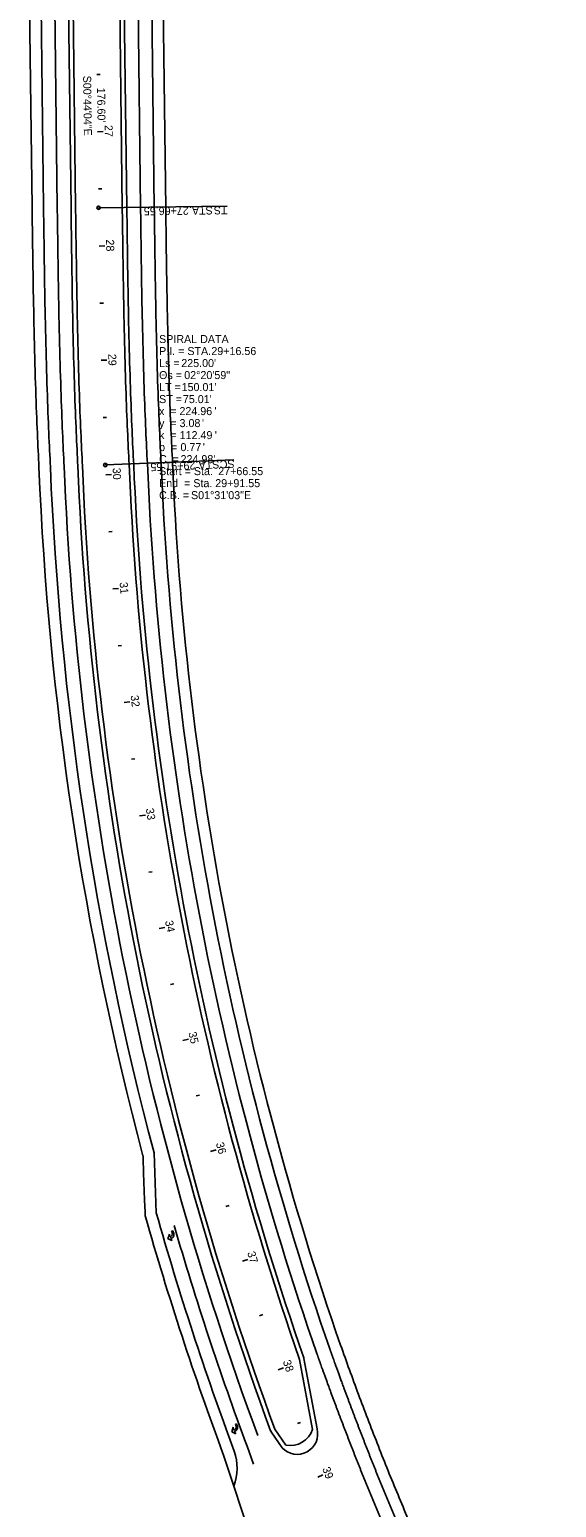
# Model space of a CAD drawing. Extents: x 76539 to 88870, y 518807 to 527554.
# Drawn here: x 87665 to 88126, y 519909 to 521202 of the extents above; entities that cross this region are included whole.
import ezdxf

# ---------------------------------------------------------------- set-up
doc = ezdxf.new("R2010")
doc.units = 0
for name, color, linetype in [('Default', 7, 'Continuous'), ('GE_P_Alignment_100_Bearings', 7, 'Continuous'), ('GE_P_Alignment_100_Cardinal_Points', 7, 'Continuous'), ('GE_P_Alignment_100_Curve_Data', 7, 'Continuous'), ('GE_P_Alignment_100_Distances', 7, 'Continuous'), ('GE_P_Alignment_100_Stations', 7, 'Continuous'), ('PM_P_Cells', 7, 'Continuous'), ('PM_P_Channelizing_Line', 7, 'Continuous'), ('PM_P_Edge_Line', 7, 'Continuous'), ('PM_P_Lane_Line', 7, 'Continuous'), ('PV_P_Joint', 7, 'Continuous'), ('PV_P_Shoulder', 7, 'Continuous'), ('XS_P_Pavt_Surface', 7, 'Continuous')]:
    doc.layers.add(name, color=color, linetype=linetype)

msp = doc.modelspace()

# ---------------------------------------------------------------- linework, layer by layer
at = {"layer": 'Default'}
for points, degree in [([(87764.1, 520216.7), (87764.1, 520215.8), (87764.1, 520214.1), (87764.2, 520211.5), (87764.3, 520208.8), (87764.4, 520206.2), (87764.5, 520203.6), (87764.5, 520201), (87764.6, 520198.4), (87764.7, 520195.7), (87764.8, 520193.1), (87764.9, 520190.5), (87765, 520187.9), (87765.1, 520185.2), (87765.2, 520182.6), (87765.3, 520180), (87765.4, 520177.3), (87765.6, 520174.7), (87765.7, 520172.1), (87765.8, 520169.5), (87765.9, 520166.8), (87766, 520165.1), (87766, 520164.2)], 3), ([(87927.4, 520047.8), (87928.8, 520043.7), (87933.9, 520029.5), (87943.4, 520003.7), (87951.1, 519983.3), (87959.5, 519961.6), (87967.9, 519940.3), (87976.6, 519919), (87985.5, 519897.8), (87994.5, 519876.7), (88003.7, 519855.7), (88013.1, 519834.7), (88022.7, 519813.8), (88032.4, 519793), (88042.4, 519772.3), (88052.5, 519751.6), (88062.8, 519731.1), (88073.2, 519710.7), (88084, 519690), (88094.2, 519670.8), (88107.3, 519646.6), (88114.7, 519633.5), (88116.8, 519629.7)], 2), ([(87936.8, 520051.1), (87939.4, 520044), (87944.5, 520029.6), (87952.4, 520008.1), (87960.5, 519986.7), (87968.8, 519965.3), (87977.2, 519944), (87985.9, 519922.8), (87994.7, 519901.7), (88003.7, 519880.6), (88012.9, 519859.7), (88022.3, 519838.8), (88031.8, 519817.9), (88041.5, 519797.2), (88051.4, 519776.6), (88061.5, 519756), (88071.7, 519735.5), (88082.1, 519715.1), (88092.7, 519694.9), (88103.5, 519674.7), (88114.4, 519654.5), (88121.8, 519641.2), (88125.5, 519634.5)], 3), ([(87916.1, 520043.7), (87917.5, 520039.7), (87922.6, 520025.4), (87932.1, 519999.5), (87939.9, 519979), (87948.3, 519957.2), (87956.8, 519935.9), (87965.5, 519914.5), (87974.4, 519893.2), (87983.5, 519871.9), (87992.8, 519850.8), (88002.2, 519829.7), (88011.8, 519808.8), (88021.6, 519787.9), (88031.6, 519767), (88041.7, 519746.3), (88052.1, 519725.7), (88062.5, 519705.2), (88073.3, 519684.4), (88083.6, 519665.1), (88096.8, 519640.9), (88104.2, 519627.6), (88106.3, 519623.9)], 2)]:
    msp.add_open_spline(points, degree=degree, dxfattribs=at)
at = {"layer": 'GE_P_Alignment_100_Cardinal_Points'}
for p, q in [((87725.2, 521045.7), (87837.7, 521047.1)), ((87731.1, 520820.8), (87843.5, 520825.4))]:
    msp.add_line(p, q, dxfattribs=at)
for centre in [(87725.2, 521045.7), (87731.1, 520820.8)]:
    msp.add_circle(centre, 1.5, dxfattribs=at)
at = {"layer": 'GE_P_Alignment_100_Stations'}
for p, q in [((87723.7, 521162.2), (87726.7, 521162.3)), ((87724.3, 521112.2), (87729.3, 521112.3)), ((87725, 521062.2), (87728, 521062.3)), ((87725.6, 521012.2), (87730.6, 521012.3)), ((87726.4, 520962.2), (87729.4, 520962.3)), ((87727.5, 520912.3), (87732.5, 520912.4)), ((87729.2, 520862.3), (87732.2, 520862.4)), ((87731.5, 520812.3), (87736.5, 520812.6)), ((87734.2, 520762.4), (87737.2, 520762.6)), ((87737.7, 520712.5), (87742.7, 520712.9)), ((87742.2, 520662.7), (87745.2, 520663)), ((87747.6, 520613), (87752.6, 520613.6)), ((87753.9, 520563.4), (87756.9, 520563.8)), ((87761.1, 520514), (87766.1, 520514.7)), ((87769.2, 520464.6), (87772.2, 520465.1)), ((87778.2, 520415.4), (87783.1, 520416.4)), ((87788.1, 520366.4), (87791, 520367)), ((87798.9, 520317.6), (87803.8, 520318.7)), ((87810.6, 520269), (87813.5, 520269.7)), ((87823.1, 520220.6), (87827.9, 520221.9)), ((87836.6, 520172.4), (87839.4, 520173.3)), ((87850.9, 520124.5), (87855.6, 520126)), ((87866, 520076.9), (87868.9, 520077.8)), ((87882.1, 520029.5), (87886.8, 520031.2)), ((87899, 519982.5), (87901.8, 519983.5)), ((87916.8, 519935.7), (87921.4, 519937.6))]:
    msp.add_line(p, q, dxfattribs=at)
at = {"layer": 'PM_P_Cells'}
for p, q in [((87786.9, 520150.1), (87786.9, 520150.1)), ((87789.1, 520150.8), (87790.1, 520151.2)), ((87789.7, 520149.1), (87789.1, 520150.8)), ((87790.1, 520151.2), (87790.9, 520148.8)), ((87785.8, 520144), (87787.2, 520148.1)), ((87789.5, 520142.5), (87785.8, 520144)), ((87787.2, 520148.1), (87787.6, 520145.9)), ((87787.6, 520145.9), (87788.3, 520146.2)), ((87788.8, 520144.6), (87788.2, 520144.4)), ((87788.2, 520144.4), (87789.5, 520142.5)), ((87789.5, 520142.5), (87789.5, 520142.5)), ((87842.6, 519981.3), (87842.6, 519981.3)), ((87844.8, 519982.1), (87845.8, 519982.4)), ((87845.4, 519980.3), (87844.8, 519982.1)), ((87845.8, 519982.4), (87846.6, 519980)), ((87841.6, 519975.2), (87842.9, 519979.4)), ((87845.2, 519973.7), (87841.6, 519975.2)), ((87842.9, 519979.4), (87843.3, 519977.1)), ((87843.3, 519977.1), (87844, 519977.4)), ((87844.5, 519975.8), (87843.9, 519975.6)), ((87843.9, 519975.6), (87845.2, 519973.7)), ((87845.2, 519973.7), (87845.2, 519973.7))]:
    msp.add_line(p, q, dxfattribs=at)
for centre, radius, start in [((87787.5, 520148.3), 2.3, 289.0234), ((87787.8, 520147.7), 3.28, 288.1149), ((87843.3, 519979.5), 2.3, 289.0234), ((87843.5, 519979), 3.28, 288.1149)]:
    msp.add_arc(centre, radius, start, 19.0234, dxfattribs=at)
at = {"layer": 'PM_P_Channelizing_Line'}
msp.add_line((87860.8, 519947.1), (87855.1, 519962.7), dxfattribs=at)
msp.add_arc((90472.1, 520933.7), 2791.4, 196.1811, 200.3571, dxfattribs=at)
at = {"layer": 'PM_P_Edge_Line'}
for p, q in [((87674.9, 521221.7), (87677.1, 521046.1)), ((87698.9, 521222), (87701.1, 521045.9)), ((87747.7, 521222.6), (87749.9, 521045.5)), ((87771.7, 521222.9), (87773.9, 521045.3)), ((87773.7, 520219.3), (87775.6, 520166.9)), ((87904.8, 520039.4), (87904.7, 520040)), ((87904.8, 520039.4), (87916.3, 519978)), ((87876.1, 519975.3), (87875.7, 519976.2)), ((87876.1, 519975.3), (87885.7, 519961.4))]:
    msp.add_line(p, q, dxfattribs=at)
for centre, radius, start, end in [((90472.1, 520933.7), 2718.5, 182.3628, 199.1928), ((90472.1, 520933.7), 2694.5, 182.3667, 199.1928), ((90472.1, 520933.7), 2791.4, 182.3509, 194.829), ((90472.1, 520933.7), 2767.4, 182.3548, 200.242), ((90472.1, 520933.7), 2803.4, 195.8733, 200.3571), ((87898.9, 519973.5), 17.9, 222.4917, 14.6896), ((87801.2, 519943.8), 45.1, 339.3713, 18.9583)]:
    msp.add_arc(centre, radius, start, end, dxfattribs=at)
for points in [[(87677.1, 521046.1), (87677.2, 521036.6), (87677.5, 521017.7), (87678, 520979.9), (87678.9, 520932.6), (87680.2, 520885.3), (87681.7, 520847.5), (87682.6, 520828.6), (87683.1, 520819.2)], [(87701.1, 521045.9), (87701.2, 521036.5), (87701.5, 521017.6), (87702, 520980), (87702.9, 520932.9), (87704.2, 520885.8), (87705.7, 520848.2), (87706.6, 520829.4), (87707.1, 520820)], [(87749.9, 521045.5), (87750.1, 521036.2), (87750.3, 521017.5), (87750.8, 520980.2), (87751.7, 520933.5), (87753, 520886.9), (87754.5, 520849.6), (87755.4, 520830.9), (87755.9, 520821.6)], [(87773.9, 521045.3), (87774.1, 521036), (87774.3, 521017.4), (87774.8, 520980.3), (87775.7, 520933.8), (87777, 520887.4), (87778.5, 520850.3), (87779.4, 520831.7), (87779.9, 520822.4)]]:
    msp.add_open_spline(points, degree=3, dxfattribs=at)
at = {"layer": 'PM_P_Lane_Line'}
for p, q in [((87686.9, 521221.8), (87689.1, 521046)), ((87759.7, 521222.7), (87761.9, 521045.4))]:
    msp.add_line(p, q, dxfattribs=at)
for radius, start, end in [(2706.5, 182.3648, 199.1928), (2779.4, 182.3528, 200.242)]:
    msp.add_arc((90472.1, 520933.7), radius, start, end, dxfattribs=at)
for points in [[(87689.1, 521046), (87689.2, 521036.5), (87689.5, 521017.7), (87690, 520979.9), (87690.9, 520932.7), (87692.2, 520885.6), (87693.7, 520847.9), (87694.6, 520829), (87695.1, 520819.6)], [(87761.9, 521045.4), (87762.1, 521036.1), (87762.3, 521017.5), (87762.8, 520980.2), (87763.7, 520933.7), (87765, 520887.1), (87766.5, 520849.9), (87767.4, 520831.3), (87767.9, 520822)]]:
    msp.add_open_spline(points, degree=3, dxfattribs=at)
at = {"layer": 'PV_P_Joint'}
msp.add_line((87834.5, 519955), (87870.6, 519845.6), dxfattribs=at)
at = {"layer": 'PV_P_Shoulder'}
for p, q in [((87664.9, 521221.5), (87667.1, 521046.1)), ((87702.9, 521222), (87705.1, 521045.8)), ((87743.7, 521222.5), (87745.9, 521045.5)), ((87781.7, 521223), (87783.9, 521045.2)), ((87900.9, 520038.7), (87912.3, 519977.3)), ((87879.4, 519977.6), (87889, 519963.7))]:
    msp.add_line(p, q, dxfattribs=at)
for centre, radius, start, end in [((90472.1, 520933.7), 2722.5, 182.3621, 199.1928), ((90472.1, 520933.7), 2684.5, 182.3684, 199.1928), ((90472.1, 520933.7), 2801.4, 182.3493, 194.829), ((90472.1, 520933.7), 2763.4, 182.3554, 200.242), ((90472.1, 520933.7), 2813.4, 195.8733, 200.3571), ((87892.8, 519984), 20.6, 259.4675, 341.1834)]:
    msp.add_arc(centre, radius, start, end, dxfattribs=at)
for points in [[(87667.1, 521046.1), (87667.2, 521036.7), (87667.5, 521017.7), (87668, 520979.8), (87668.9, 520932.5), (87670.2, 520885.1), (87671.7, 520847.2), (87672.6, 520828.3), (87673.1, 520818.9)], [(87705.1, 521045.8), (87705.2, 521036.4), (87705.5, 521017.6), (87706, 520980), (87706.9, 520932.9), (87708.2, 520885.9), (87709.7, 520848.3), (87710.6, 520829.5), (87711.1, 520820.1)], [(87745.9, 521045.5), (87746.1, 521036.2), (87746.3, 521017.5), (87746.8, 520980.2), (87747.7, 520933.5), (87749, 520886.8), (87750.5, 520849.5), (87751.4, 520830.8), (87751.9, 520821.5)], [(87783.9, 521045.2), (87784.1, 521036), (87784.3, 521017.4), (87784.8, 520980.3), (87785.7, 520934), (87787, 520887.6), (87788.5, 520850.5), (87789.4, 520832), (87789.9, 520822.7)]]:
    msp.add_open_spline(points, degree=3, dxfattribs=at)
at = {"layer": 'XS_P_Pavt_Surface'}
for p, q in [((87667.1, 521046.1), (87664.9, 521221.5)), ((87702.9, 521222), (87705.1, 521045.8)), ((87745.9, 521045.5), (87743.7, 521222.5)), ((87781.7, 521223), (87783.9, 521045.2)), ((87912.3, 519977.3), (87900.9, 520038.7)), ((87879.4, 519977.6), (87889, 519963.7)), ((87870.6, 519845.6), (87834.5, 519955))]:
    msp.add_line(p, q, dxfattribs=at)
for centre, radius, start, end in [((90472.1, 520933.7), 2722.5, 182.3621, 199.1928), ((90472.1, 520933.7), 2684.5, 182.3684, 199.1928), ((90472.1, 520933.7), 2801.4, 182.3493, 194.829), ((90472.1, 520933.7), 2763.4, 182.3554, 200.242), ((90472.1, 520933.7), 2813.4, 195.8733, 200.3571), ((87892.8, 519984), 20.6, 259.4675, 341.1834)]:
    msp.add_arc(centre, radius, start, end, dxfattribs=at)
for points in [[(87673.1, 520818.9), (87672.6, 520828.3), (87671.7, 520847.2), (87670.2, 520885.1), (87668.9, 520932.5), (87668, 520979.8), (87667.5, 521017.7), (87667.2, 521036.7), (87667.1, 521046.1)], [(87705.1, 521045.8), (87705.2, 521036.4), (87705.5, 521017.6), (87706, 520980), (87706.9, 520932.9), (87708.2, 520885.9), (87709.7, 520848.3), (87710.6, 520829.5), (87711.1, 520820.1)], [(87751.9, 520821.5), (87751.4, 520830.8), (87750.5, 520849.5), (87749, 520886.8), (87747.7, 520933.5), (87746.8, 520980.2), (87746.3, 521017.5), (87746.1, 521036.2), (87745.9, 521045.5)], [(87783.9, 521045.2), (87784.1, 521036), (87784.3, 521017.4), (87784.8, 520980.3), (87785.7, 520934), (87787, 520887.6), (87788.5, 520850.5), (87789.4, 520832), (87789.9, 520822.7)], [(87766, 520164.2), (87766, 520165.1), (87765.9, 520166.8), (87765.8, 520169.5), (87765.7, 520172.1), (87765.6, 520174.7), (87765.4, 520177.3), (87765.3, 520180), (87765.2, 520182.6), (87765.1, 520185.2), (87765, 520187.9), (87764.9, 520190.5), (87764.8, 520193.1), (87764.7, 520195.7), (87764.6, 520198.4), (87764.5, 520201), (87764.5, 520203.6), (87764.4, 520206.2), (87764.3, 520208.8), (87764.2, 520211.5), (87764.1, 520214.1), (87764.1, 520215.8), (87764.1, 520216.7)], [(87936.8, 520051.1), (87939.4, 520044), (87944.5, 520029.6), (87952.4, 520008.1), (87960.5, 519986.7), (87968.8, 519965.3), (87977.2, 519944), (87985.9, 519922.8), (87994.7, 519901.7), (88003.7, 519880.6), (88012.9, 519859.7), (88022.3, 519838.8), (88031.8, 519817.9), (88041.5, 519797.2), (88051.4, 519776.6), (88061.5, 519756), (88071.7, 519735.5), (88082.1, 519715.1), (88092.7, 519694.9), (88103.5, 519674.7), (88114.4, 519654.5), (88121.8, 519641.2), (88125.5, 519634.5)]]:
    msp.add_open_spline(points, degree=3, dxfattribs=at)

# ---------------------------------------------------------------- texts
at = {"layer": 'GE_P_Alignment_100_Bearings'}
msp.add_text('S00°44\'04"E', height=7, rotation=270.7344, dxfattribs=at).set_placement((87711.7, 521161.2))
at = {"layer": 'GE_P_Alignment_100_Cardinal_Points'}
for s, rotation, p in [('27+66.55', 180.7344, (87804, 521046.6)), (' STA. ', 180.7344, (87827.6, 521046.9)), ('TS', 180.7344, (87837.9, 521047)), ('29+91.55', 182.3587, (87809.7, 520823.9)), (' STA. ', 182.3587, (87833.3, 520824.9)), ('SC', 182.3587, (87844, 520825.3))]:
    msp.add_text(s, height=7, rotation=rotation, dxfattribs=at).set_placement(p)
at = {"layer": 'GE_P_Alignment_100_Curve_Data'}
for s, p in [('SPIRAL DATA', (87778.1, 520927.4)), ('P.I. = STA. ', (87778.1, 520916.9)), ('29+16.56', (87823.8, 520916.9)), ('Ls = ', (87778.1, 520906.4)), ("225.00'", (87797.5, 520906.4)), ('Θs = ', (87778.1, 520895.9)), ('02°20\'59"', (87800.1, 520895.9)), ('LT = ', (87778.1, 520885.4)), ("150.01'", (87797.8, 520885.4)), ('ST = ', (87778.1, 520874.9)), ("75.01'", (87798.9, 520874.9)), ('x  = ', (87778.1, 520864.4)), ('y  = ', (87778.1, 520853.9)), ('224.96', (87795.9, 520864.4)), ('3.08', (87796, 520853.9)), ("'", (87815.6, 520853.9)), ("'", (87826.6, 520864.4)), ('k  = ', (87778.1, 520843.4)), ('112.49', (87796.1, 520843.4)), ("'", (87826.8, 520843.4)), ('p  = ', (87778.1, 520832.9)), ('0.77', (87796.8, 520832.9)), ("'", (87816.3, 520832.9)), ('C  = ', (87778.1, 520822.4)), ("224.98'", (87796.9, 520822.4)), ('Start = Sta. ', (87778.1, 520811.9)), ('End  = Sta. ', (87778.1, 520801.4)), ('29+91.55', (87827.2, 520801.4)), ('27+66.55', (87829.8, 520811.9)), ('C.B. = ', (87778.1, 520790.9)), ('S01°31\'03"E', (87806, 520790.9))]:
    msp.add_text(s, height=7, dxfattribs=at).set_placement(p)
at = {"layer": 'GE_P_Alignment_100_Distances'}
msp.add_text("176.60'", height=7, rotation=270.7344, dxfattribs=at).set_placement((87723.9, 521150.7))
at = {"layer": 'GE_P_Alignment_100_Stations'}
for s, rotation, p in [('27', 270.7344, (87730.5, 521118.1)), ('28', 270.7863, (87731.8, 521017.9)), ('29', 271.5609, (87733.6, 520917.9)), ('30', 272.5352, (87737.5, 520818.2)), ('31', 274.6237, (87743.6, 520718.1)), ('32', 276.7123, (87753.2, 520619.1)), ('33', 278.8009, (87766.5, 520520.2)), ('34', 280.8894, (87783.3, 520421.9)), ('35', 282.978, (87803.7, 520324.3)), ('36', 285.0666, (87827.7, 520227.6)), ('37', 287.1551, (87855.1, 520131.9)), ('38', 289.2437, (87886.2, 520036.8)), ('39', 291.3323, (87920.6, 519943.1))]:
    msp.add_text(s, height=7, rotation=rotation, dxfattribs=at).set_placement(p)

doc.saveas('drawing.dxf')
